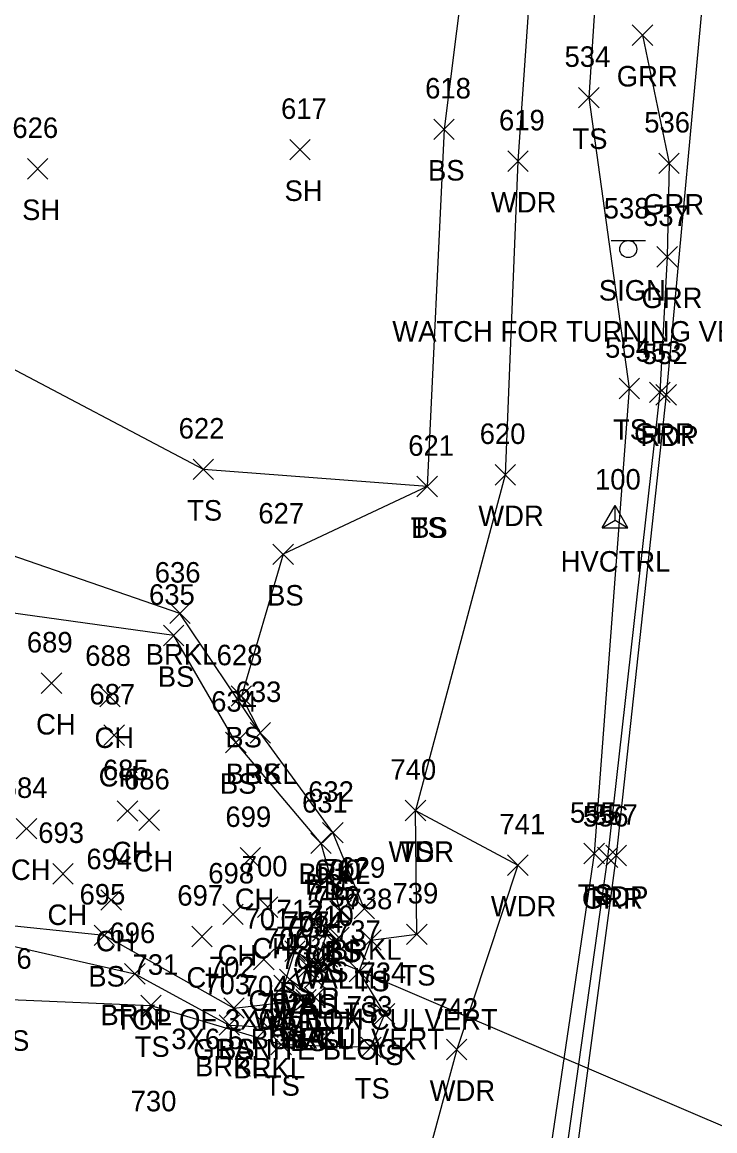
# Model space of a CAD drawing. Extents: x 1638705 to 1644019, y 630225 to 637423.
# Drawn here: x 1643815.9 to 1643883.4, y 637066.8 to 637174.9 of the extents above; entities that cross this region are included whole.
import ezdxf

# ---------------------------------------------------------------- set-up
doc = ezdxf.new("R2010")
doc.units = 0
for name, color, linetype in [('C_A', 7, 'Continuous'), ('C_I', 7, 'Continuous'), ('CPSM', 7, 'Continuous'), ('D_A', 7, 'Continuous'), ('D_C', 7, 'Continuous'), ('D_I', 7, 'Continuous'), ('D_TIC', 7, 'Continuous'), ('DCP', 7, 'Continuous'), ('DHW', 7, 'Continuous'), ('L_A', 7, 'Continuous'), ('L_C', 7, 'Continuous'), ('L_I', 7, 'Continuous'), ('L_TIC', 7, 'Continuous'), ('LAWA', 7, 'Continuous'), ('LAWE', 7, 'Continuous'), ('LELB', 7, 'Continuous'), ('LW', 7, 'Continuous'), ('P_A', 7, 'Continuous'), ('P_I', 7, 'Continuous'), ('P_TIC', 7, 'Continuous'), ('PET', 7, 'Continuous'), ('R_A', 7, 'Continuous'), ('R_I', 7, 'Continuous'), ('R_TIC', 7, 'Continuous'), ('RGR', 7, 'Continuous'), ('S_A', 7, 'Continuous'), ('S_C', 7, 'Continuous'), ('S_I', 7, 'Continuous'), ('SSGN', 7, 'Continuous')]:
    doc.layers.add(name, color=color, linetype=linetype)

msp = doc.modelspace()

# ---------------------------------------------------------------- linework, layer by layer
at = {"layer": 'CPSM'}
for p, q in [((1643872.43, 637125.61), (1643873.68, 637127.77)), ((1643874.93, 637125.61), (1643873.68, 637127.77)), ((1643873.68, 637126.33), (1643873.68, 637127.77)), ((1643872.43, 637125.61), (1643873.68, 637126.33)), ((1643872.43, 637125.61), (1643874.93, 637125.61)), ((1643873.68, 637126.33), (1643873.68, 637126.33)), ((1643873.68, 637126.33), (1643874.93, 637125.61))]:
    msp.add_line(p, q, dxfattribs=at)
at = {"layer": 'D_TIC'}
for points in [[(1643845.75, 637084.68), (1643847.75, 637086.68)], [(1643847.75, 637084.68), (1643845.75, 637086.68)], [(1643844.62, 637082.78), (1643846.62, 637084.78)], [(1643846.62, 637082.78), (1643844.62, 637084.78)], [(1643843.39, 637080.73), (1643845.39, 637082.73)], [(1643845.39, 637080.73), (1643843.39, 637082.73)]]:
    msp.add_lwpolyline(points, dxfattribs=at)
at = {"layer": 'DCP'}
msp.add_lwpolyline([(1643845.62, 637083.78), (1643920.02, 637051.96)], dxfattribs=at)
at = {"layer": 'DHW'}
msp.add_lwpolyline([(1643844.39, 637081.73), (1643846.75, 637085.68)], dxfattribs=at)
at = {"layer": 'L_TIC'}
for points in [[(1643870.11, 637166.53), (1643872.11, 637168.53)], [(1643872.11, 637166.53), (1643870.11, 637168.53)], [(1643856, 637163.45), (1643858, 637165.45)], [(1643858, 637163.45), (1643856, 637165.45)], [(1643841.96, 637161.46), (1643843.96, 637163.46)], [(1643843.96, 637161.46), (1643841.96, 637163.46)], [(1643863.21, 637160.34), (1643865.21, 637162.34)], [(1643865.21, 637160.34), (1643863.21, 637162.34)], [(1643816.38, 637159.6), (1643818.38, 637161.6)], [(1643818.38, 637159.6), (1643816.38, 637161.6)], [(1643874.06, 637138.18), (1643876.06, 637140.18)], [(1643876.06, 637138.18), (1643874.06, 637140.18)], [(1643832.54, 637130.3), (1643834.54, 637132.3)], [(1643834.54, 637130.3), (1643832.54, 637132.3)], [(1643861.97, 637129.77), (1643863.97, 637131.77)], [(1643863.97, 637129.77), (1643861.97, 637131.77)], [(1643854.35, 637128.62), (1643856.35, 637130.62)], [(1643856.35, 637128.62), (1643854.35, 637130.62)], [(1643854.35, 637128.62), (1643856.35, 637130.62)], [(1643856.35, 637128.62), (1643854.35, 637130.62)], [(1643840.31, 637122.02), (1643842.31, 637124.02)], [(1643842.31, 637122.02), (1643840.31, 637124.02)], [(1643830.26, 637116.26), (1643832.26, 637118.26)], [(1643832.26, 637116.26), (1643830.26, 637118.26)], [(1643829.65, 637114.1), (1643831.65, 637116.1)], [(1643831.65, 637114.1), (1643829.65, 637116.1)], [(1643817.74, 637109.45), (1643819.74, 637111.45)], [(1643819.74, 637109.45), (1643817.74, 637111.45)], [(1643823.43, 637108.14), (1643825.43, 637110.14)], [(1643825.43, 637108.14), (1643823.43, 637110.14)], [(1643836.24, 637108.2), (1643838.24, 637110.2)], [(1643838.24, 637108.2), (1643836.24, 637110.2)], [(1643823.84, 637104.38), (1643825.84, 637106.38)], [(1643825.84, 637104.38), (1643823.84, 637106.38)], [(1643838.09, 637104.62), (1643840.09, 637106.62)], [(1643840.09, 637104.62), (1643838.09, 637106.62)], [(1643838.09, 637104.62), (1643840.09, 637106.62)], [(1643840.09, 637104.62), (1643838.09, 637106.62)], [(1643835.71, 637103.68), (1643837.71, 637105.68)], [(1643837.71, 637103.68), (1643835.71, 637105.68)], [(1643825.15, 637097), (1643827.15, 637099)], [(1643827.15, 637097), (1643825.15, 637099)], [(1643853.22, 637097.04), (1643855.22, 637099.04)], [(1643855.22, 637097.04), (1643853.22, 637099.04)], [(1643853.22, 637097.04), (1643855.22, 637099.04)], [(1643855.22, 637097.04), (1643853.22, 637099.04)], [(1643827.26, 637096.1), (1643829.26, 637098.1)], [(1643829.26, 637096.1), (1643827.26, 637098.1)], [(1643815.29, 637095.27), (1643817.29, 637097.27)], [(1643817.29, 637095.27), (1643815.29, 637097.27)], [(1643845.16, 637094.89), (1643847.16, 637096.89)], [(1643847.16, 637094.89), (1643845.16, 637096.89)], [(1643844.01, 637093.84), (1643846.01, 637095.84)], [(1643846.01, 637093.84), (1643844.01, 637095.84)], [(1643837.11, 637092.44), (1643839.11, 637094.44)], [(1643839.11, 637092.44), (1643837.11, 637094.44)], [(1643870.64, 637092.85), (1643872.64, 637094.85)], [(1643872.64, 637092.85), (1643870.64, 637094.85)], [(1643863.2, 637091.72), (1643865.2, 637093.72)], [(1643865.2, 637091.72), (1643863.2, 637093.72)], [(1643818.85, 637090.88), (1643820.85, 637092.88)], [(1643820.85, 637090.88), (1643818.85, 637092.88)], [(1643823.55, 637088.32), (1643825.55, 637090.32)], [(1643825.55, 637088.32), (1643823.55, 637090.32)], [(1643835.43, 637086.93), (1643837.43, 637088.93)], [(1643837.43, 637086.93), (1643835.43, 637088.93)], [(1643838.81, 637087.62), (1643840.81, 637089.62)], [(1643840.81, 637087.62), (1643838.81, 637089.62)], [(1643845.87, 637087.25), (1643847.87, 637089.25)], [(1643847.87, 637087.25), (1643845.87, 637089.25)], [(1643845.99, 637087.33), (1643847.99, 637089.33)], [(1643847.99, 637087.33), (1643845.99, 637089.33)], [(1643848.23, 637087.49), (1643850.23, 637089.49)], [(1643850.23, 637087.49), (1643848.23, 637089.49)], [(1643822.88, 637084.88), (1643824.88, 637086.88)], [(1643824.88, 637084.88), (1643822.88, 637086.88)], [(1643832.4, 637084.77), (1643834.4, 637086.77)], [(1643834.4, 637084.77), (1643832.4, 637086.77)], [(1643844.17, 637085.3), (1643846.17, 637087.3)], [(1643846.17, 637085.3), (1643844.17, 637087.3)], [(1643844.69, 637085.32), (1643846.69, 637087.32)], [(1643846.69, 637085.32), (1643844.69, 637087.32)], [(1643853.35, 637084.98), (1643855.35, 637086.98)], [(1643855.35, 637084.98), (1643853.35, 637086.98)], [(1643848.86, 637084.42), (1643850.86, 637086.42)], [(1643850.86, 637084.42), (1643848.86, 637086.42)], [(1643838.44, 637082.52), (1643840.44, 637084.52)], [(1643840.44, 637082.52), (1643838.44, 637084.52)], [(1643841.47, 637083.34), (1643843.47, 637085.34)], [(1643843.47, 637083.34), (1643841.47, 637085.34)], [(1643842.81, 637082.21), (1643844.81, 637084.21)], [(1643844.81, 637082.21), (1643842.81, 637084.21)], [(1643842.81, 637081.76), (1643844.81, 637083.76)], [(1643844.81, 637081.76), (1643842.81, 637083.76)], [(1643843.49, 637082.14), (1643845.49, 637084.14)], [(1643845.49, 637082.14), (1643843.49, 637084.14)], [(1643847.74, 637081.34), (1643849.74, 637083.34)], [(1643849.74, 637081.34), (1643847.74, 637083.34)], [(1643825.85, 637081.12), (1643827.85, 637083.12)], [(1643827.85, 637081.12), (1643825.85, 637083.12)], [(1643840.95, 637080.57), (1643842.95, 637082.57)], [(1643842.95, 637080.57), (1643840.95, 637082.57)], [(1643840.41, 637080.01), (1643842.41, 637082.01)], [(1643842.41, 637080.01), (1643840.41, 637082.01)], [(1643827.43, 637078.03), (1643829.43, 637080.03)], [(1643829.43, 637078.03), (1643827.43, 637080.03)], [(1643842.54, 637078.59), (1643844.54, 637080.59)], [(1643844.54, 637078.59), (1643842.54, 637080.59)], [(1643843.4, 637078.83), (1643845.4, 637080.83)], [(1643845.4, 637078.83), (1643843.4, 637080.83)], [(1643843.4, 637078.83), (1643845.4, 637080.83)], [(1643845.4, 637078.83), (1643843.4, 637080.83)], [(1643835.52, 637077.79), (1643837.52, 637079.79)], [(1643837.52, 637077.79), (1643835.52, 637079.79)], [(1643850.22, 637077.23), (1643852.22, 637079.23)], [(1643852.22, 637077.23), (1643850.22, 637079.23)], [(1643835.07, 637076.13), (1643837.07, 637078.13)], [(1643837.07, 637076.13), (1643835.07, 637078.13)], [(1643838.82, 637075.93), (1643840.82, 637077.93)], [(1643840.82, 637075.93), (1643838.82, 637077.93)], [(1643840.12, 637074.24), (1643842.12, 637076.24)], [(1643842.12, 637074.24), (1643840.12, 637076.24)], [(1643848.88, 637073.96), (1643850.88, 637075.96)], [(1643850.88, 637073.96), (1643848.88, 637075.96)], [(1643857.24, 637073.74), (1643859.24, 637075.74)], [(1643859.24, 637073.74), (1643857.24, 637075.74)]]:
    msp.add_lwpolyline(points, dxfattribs=at)
at = {"layer": 'LAWA'}
msp.add_lwpolyline([(1643865.64, 637303.77), (1643862.82, 637270.27), (1643861.25, 637253.7), (1643870.99, 637241.9), (1643867.11, 637203.42), (1643864.21, 637161.34), (1643862.97, 637130.77), (1643854.22, 637098.04), (1643864.2, 637092.72), (1643858.24, 637074.74), (1643852.38, 637053.09), (1643849.03, 637029.11), (1643850.77, 637013.92), (1643837.37, 636980.48), (1643832.85, 636980.73), (1643828.82, 636965.18), (1643821.8, 636940.41), (1643821.76, 636915.63), (1643813.91, 636882.55), (1643810.67, 636866.31)], dxfattribs=at)
at = {"layer": 'LAWE'}
for points in [[(1643849.23, 637088.49), (1643846.16, 637095.89), (1643839.09, 637105.62), (1643831.26, 637117.26), (1643809.52, 637124.74), (1643785.58, 637114.55), (1643772.85, 637123.27), (1643766.46, 637133.19), (1643755.78, 637139.46)], [(1643737.09, 637111.66), (1643752.11, 637122.35), (1643762, 637112.4), (1643768.69, 637097.71), (1643785.02, 637093.15), (1643799.41, 637088.46), (1643811.25, 637085.66), (1643826.85, 637082.12), (1643836.07, 637077.13), (1643839.82, 637076.93), (1643844.4, 637079.83)]]:
    msp.add_lwpolyline(points, dxfattribs=at)
at = {"layer": 'LELB'}
for points in [[(1643865.64, 637303.77), (1643868.54, 637268.73), (1643861.25, 637253.7), (1643861.87, 637202.97), (1643857, 637164.45), (1643855.35, 637129.62), (1643841.31, 637123.02), (1643837.24, 637109.2), (1643839.09, 637105.62)], [(1643881.31, 637303.51), (1643880.47, 637260.36), (1643877.75, 637219.48), (1643872.16, 637183.49), (1643871.11, 637167.53), (1643875.06, 637139.18), (1643871.64, 637093.85), (1643865.67, 637053.39), (1643855.97, 637011.76), (1643842.4, 636975.8), (1643838.3, 636921.94), (1643830.67, 636893.45), (1643822.68, 636863.82)], [(1643855.35, 637129.62), (1643833.54, 637131.3), (1643812.95, 637142.13), (1643787.29, 637143.99), (1643791.25, 637159.07)], [(1643738.9, 637116.56), (1643749.87, 637124.53), (1643762.67, 637115.99), (1643769.88, 637099.38), (1643785.95, 637095.12), (1643800.85, 637092.37), (1643811.99, 637087.14), (1643823.88, 637085.88), (1643836.52, 637078.79), (1643843.54, 637079.59), (1643841.41, 637081.01), (1643842.47, 637084.34), (1643844.49, 637083.14), (1643845.69, 637086.32), (1643845.17, 637086.3), (1643846.99, 637088.33)], [(1643846.87, 637088.25), (1643845.01, 637094.84), (1643836.71, 637104.68), (1643830.65, 637115.1), (1643805.86, 637118.55), (1643784.63, 637112.92)], [(1643751.12, 637107.36), (1643763.89, 637095.24), (1643783.74, 637086.53), (1643793.4, 637085.68), (1643814.75, 637079.62), (1643828.43, 637079.03), (1643841.12, 637075.24), (1643849.88, 637074.96), (1643851.22, 637078.23), (1643848.74, 637082.34), (1643849.86, 637085.42), (1643854.35, 637085.98), (1643854.22, 637098.04)]]:
    msp.add_lwpolyline(points, dxfattribs=at)
at = {"layer": 'LW'}
msp.add_lwpolyline([(1643844.4, 637079.83), (1643841.95, 637081.57), (1643843.81, 637083.21), (1643843.81, 637082.76)], dxfattribs=at)
at = {"layer": 'P_TIC'}
for points in [[(1643877.66, 637137.56), (1643879.66, 637139.56)], [(1643879.66, 637137.56), (1643877.66, 637139.56)], [(1643872.79, 637092.66), (1643874.79, 637094.66)], [(1643874.79, 637092.66), (1643872.79, 637094.66)]]:
    msp.add_lwpolyline(points, dxfattribs=at)
at = {"layer": 'PET'}
msp.add_lwpolyline([(1643886.09, 637303.33), (1643885.33, 637260.95), (1643884.29, 637219.34), (1643882.65, 637181.95), (1643878.66, 637138.56), (1643873.79, 637093.66), (1643868.41, 637053.44), (1643859.66, 637004.66), (1643851.59, 636964.82), (1643841.08, 636921.12), (1643833.58, 636892.49), (1643824.77, 636863.46)], dxfattribs=at)
at = {"layer": 'R_TIC'}
for points in [[(1643875.35, 637172.62), (1643877.35, 637174.62)], [(1643877.35, 637172.62), (1643875.35, 637174.62)], [(1643877.94, 637160.13), (1643879.94, 637162.13)], [(1643879.94, 637160.13), (1643877.94, 637162.13)], [(1643877.76, 637151.02), (1643879.76, 637153.02)], [(1643879.76, 637151.02), (1643877.76, 637153.02)], [(1643877.04, 637137.8), (1643879.04, 637139.8)], [(1643879.04, 637137.8), (1643877.04, 637139.8)], [(1643871.95, 637092.48), (1643873.95, 637094.48)], [(1643873.95, 637092.48), (1643871.95, 637094.48)]]:
    msp.add_lwpolyline(points, dxfattribs=at)
at = {"layer": 'RGR'}
msp.add_lwpolyline([(1643876.35, 637173.62), (1643878.94, 637161.13), (1643878.76, 637152.02), (1643878.04, 637138.8), (1643872.95, 637093.48), (1643867.32, 637053.41), (1643859.11, 637005.06), (1643857.05, 636995.48), (1643852.66, 636983.49), (1643847.82, 636974.92)], dxfattribs=at)
at = {"layer": 'SSGN'}
for p, q in [((1643873.31, 637153.61), (1643876.64, 637153.61)), ((1643874.96, 637152.77), (1643874.96, 637152.77))]:
    msp.add_line(p, q, dxfattribs=at)
msp.add_circle((1643874.96, 637152.77), 0.833, dxfattribs=at)

# ---------------------------------------------------------------- texts
at = {"layer": 'C_A'}
msp.add_text('HVCTRL', height=2, dxfattribs=at).set_placement((1643868.37, 637121.33))
at = {"layer": 'C_I'}
msp.add_text('100', height=2, dxfattribs=at).set_placement((1643871.72, 637129.33))
at = {"layer": 'D_A'}
for s, p in [('WALLH', (1643842.34, 637080.68)), ('P', (1643845, 637078.78)), ('WALLH', (1643839.98, 637076.73))]:
    msp.add_text(s, height=2, dxfattribs=at).set_placement(p)
at = {"layer": 'D_C'}
for s, p in [('TOP OF 3X6.5 BOX CULVERT', (1643824.93, 637076.68)), ('3X6.5 BOX CULVERT', (1643830.41, 637074.78))]:
    msp.add_text(s, height=2, dxfattribs=at).set_placement(p)
at = {"layer": 'D_I'}
for s, p in [('736', (1643844.34, 637088.68)), ('710', (1643843.74, 637086.78)), ('735', (1643842.03, 637084.73))]:
    msp.add_text(s, height=2, dxfattribs=at).set_placement(p)
at = {"layer": 'L_A'}
for s, p in [('TS', (1643869.52, 637162.53)), ('BS', (1643855.44, 637159.45)), ('SH', (1643841.45, 637157.46)), ('WDR', (1643861.57, 637156.34)), ('SH', (1643815.87, 637155.6)), ('TS', (1643873.47, 637134.18)), ('TS', (1643831.95, 637126.3)), ('WDR', (1643860.34, 637125.77)), ('TS', (1643853.76, 637124.62)), ('BS', (1643853.79, 637124.62)), ('BS', (1643839.75, 637118.02)), ('BRKL', (1643827.91, 637112.26)), ('BS', (1643829.09, 637110.1)), ('CH', (1643817.23, 637105.45)), ('CH', (1643822.92, 637104.14)), ('BS', (1643835.68, 637104.2)), ('CH', (1643823.33, 637100.38)), ('BS', (1643835.15, 637099.68)), ('BRKL', (1643835.73, 637100.62)), ('BS', (1643837.53, 637100.62)), ('CH', (1643824.63, 637093)), ('CH', (1643826.75, 637092.1)), ('WDR', (1643851.59, 637093.04)), ('TS', (1643852.63, 637093.04)), ('CH', (1643814.78, 637091.27)), ('BRKL', (1643842.81, 637090.89)), ('BS', (1643843.45, 637089.84)), ('TS', (1643870.05, 637088.85)), ('CH', (1643836.6, 637088.44)), ('CH', (1643818.34, 637086.88)), ('WDR', (1643861.56, 637087.72)), ('CH', (1643823.04, 637084.32)), ('CH', (1643838.3, 637083.62)), ('BRKL', (1643845.87, 637083.49)), ('CH', (1643834.92, 637082.93)), ('BS', (1643845.31, 637083.25)), ('BS', (1643845.43, 637083.33)), ('BS', (1643843.62, 637081.3)), ('BS', (1643844.13, 637081.32)), ('BS', (1643822.32, 637080.88)), ('CH', (1643831.89, 637080.77)), ('TS', (1643848.27, 637080.42)), ('TS', (1643852.76, 637080.98)), ('BS', (1643840.91, 637079.34)), ('CH', (1643837.93, 637078.52)), ('WALL', (1643840.3, 637078.21)), ('BS', (1643842.94, 637078.14)), ('BRKL', (1643823.5, 637077.12)), ('WALL', (1643840.29, 637077.76)), ('TS', (1643847.15, 637077.34)), ('WALL', (1643838.44, 637076.57)), ('BS', (1643839.85, 637076.01)), ('WALL', (1643840.89, 637074.83)), ('BRKL', (1643841.05, 637074.83)), ('TS', (1643813.16, 637074.62)), ('TS', (1643826.84, 637074.03)), ('BS', (1643834.97, 637073.79)), ('BS', (1643841.99, 637074.59)), ('TS', (1643849.63, 637073.23)), ('BRKL', (1643832.72, 637072.13)), ('BRKL', (1643836.47, 637071.93)), ('TS', (1643839.53, 637070.24)), ('TS', (1643848.29, 637069.96)), ('WDR', (1643855.6, 637069.74))]:
    msp.add_text(s, height=2, dxfattribs=at).set_placement(p)
at = {"layer": 'L_C'}
msp.add_text('GRANITE BLOCK', height=2, dxfattribs=at).set_placement((1643832.56, 637073.76))
at = {"layer": 'L_I'}
for s, p in [('534', (1643868.75, 637170.53)), ('618', (1643855.16, 637167.45)), ('617', (1643841.11, 637165.46)), ('626', (1643814.92, 637163.6)), ('619', (1643862.36, 637164.34)), ('554', (1643872.7, 637142.18)), ('622', (1643831.13, 637134.3)), ('620', (1643860.48, 637133.77)), ('621', (1643853.51, 637132.62)), ('621', (1643853.51, 637132.62)), ('627', (1643838.9, 637126.02)), ('636', (1643828.8, 637120.26)), ('635', (1643828.24, 637118.1)), ('689', (1643816.33, 637113.45)), ('688', (1643822.02, 637112.14)), ('628', (1643834.83, 637112.2)), ('687', (1643822.43, 637108.38)), ('633', (1643836.68, 637108.62)), ('633', (1643836.68, 637108.62)), ('634', (1643834.3, 637107.68)), ('685', (1643823.74, 637101)), ('740', (1643851.77, 637101.04)), ('740', (1643851.77, 637101.04)), ('686', (1643825.8, 637100.1)), ('684', (1643813.88, 637099.27)), ('632', (1643843.75, 637098.89)), ('631', (1643843.16, 637097.84)), ('699', (1643835.69, 637096.44)), ('555', (1643869.28, 637096.85)), ('741', (1643862.4, 637095.72)), ('693', (1643817.44, 637094.88)), ('694', (1643822.14, 637092.32)), ('700', (1643837.28, 637091.62)), ('630', (1643844.37, 637091.25)), ('717', (1643845.19, 637091.33)), ('629', (1643846.81, 637091.49)), ('698', (1643834.02, 637090.93)), ('695', (1643821.47, 637088.88)), ('716', (1643843.32, 637089.3)), ('715', (1643843.9, 637089.32)), ('739', (1643851.98, 637088.98)), ('697', (1643831, 637088.77)), ('738', (1643847.5, 637088.42)), ('712', (1643840.68, 637087.34)), ('701', (1643837.56, 637086.52)), ('708', (1643841.37, 637085.76)), ('707', (1643841.37, 637086.21)), ('714', (1643842.7, 637086.14)), ('696', (1643824.39, 637085.12)), ('706', (1643839.45, 637084.57)), ('737', (1643846.38, 637085.34)), ('711', (1643840.18, 637084.01)), ('726', (1643812.34, 637082.62)), ('709', (1643841.1, 637082.59)), ('705', (1643841.96, 637082.83)), ('705', (1643841.96, 637082.83)), ('731', (1643826.64, 637082.03)), ('702', (1643834.08, 637081.79)), ('734', (1643848.86, 637081.23)), ('703', (1643833.63, 637080.13)), ('704', (1643837.38, 637079.93)), ('732', (1643838.76, 637078.24)), ('733', (1643847.51, 637077.96)), ('742', (1643855.87, 637077.74)), ('730', (1643826.45, 637068.72))]:
    msp.add_text(s, height=2, dxfattribs=at).set_placement(p)
at = {"layer": 'P_A'}
for p in [(1643876.15, 637133.56), (1643871.28, 637088.66)]:
    msp.add_text('RDP', height=2, dxfattribs=at).set_placement(p)
at = {"layer": 'P_I'}
for s, p in [('552', (1643876.3, 637141.56)), ('557', (1643871.43, 637096.66))]:
    msp.add_text(s, height=2, dxfattribs=at).set_placement(p)
at = {"layer": 'R_A'}
for p in [(1643873.84, 637168.62), (1643876.42, 637156.13), (1643876.25, 637147.02), (1643875.53, 637133.8), (1643870.44, 637088.48)]:
    msp.add_text('GRR', height=2, dxfattribs=at).set_placement(p)
at = {"layer": 'R_I'}
for s, p in [('536', (1643876.52, 637164.13)), ('537', (1643876.4, 637155.02)), ('553', (1643875.68, 637141.8)), ('556', (1643870.53, 637096.48))]:
    msp.add_text(s, height=2, dxfattribs=at).set_placement(p)
at = {"layer": 'S_A'}
msp.add_text('SIGN', height=2, dxfattribs=at).set_placement((1643872.09, 637147.75))
at = {"layer": 'S_C'}
msp.add_text('WATCH FOR TURNING VEHICLES', height=2, dxfattribs=at).set_placement((1643851.96, 637143.75))
at = {"layer": 'S_I'}
msp.add_text('538', height=2, dxfattribs=at).set_placement((1643872.57, 637155.75))

doc.saveas('drawing.dxf')
